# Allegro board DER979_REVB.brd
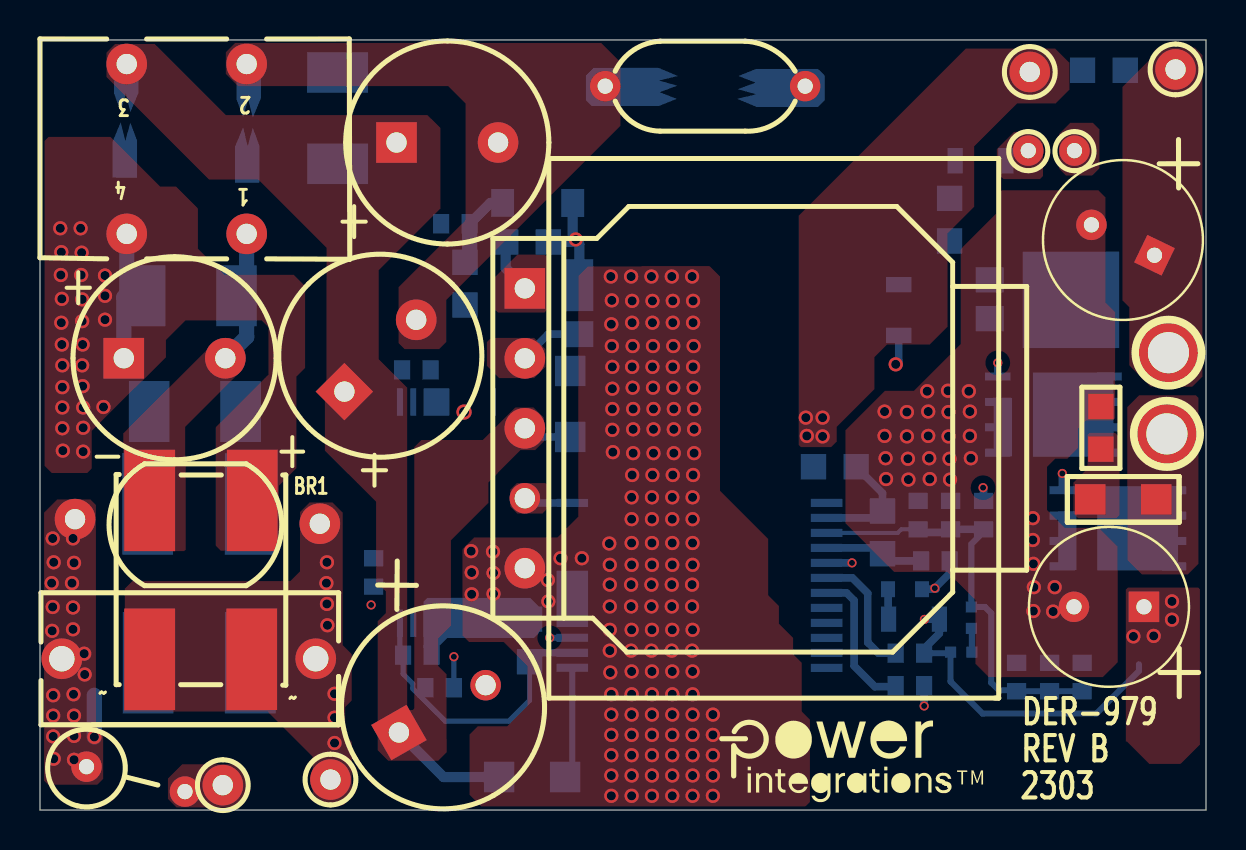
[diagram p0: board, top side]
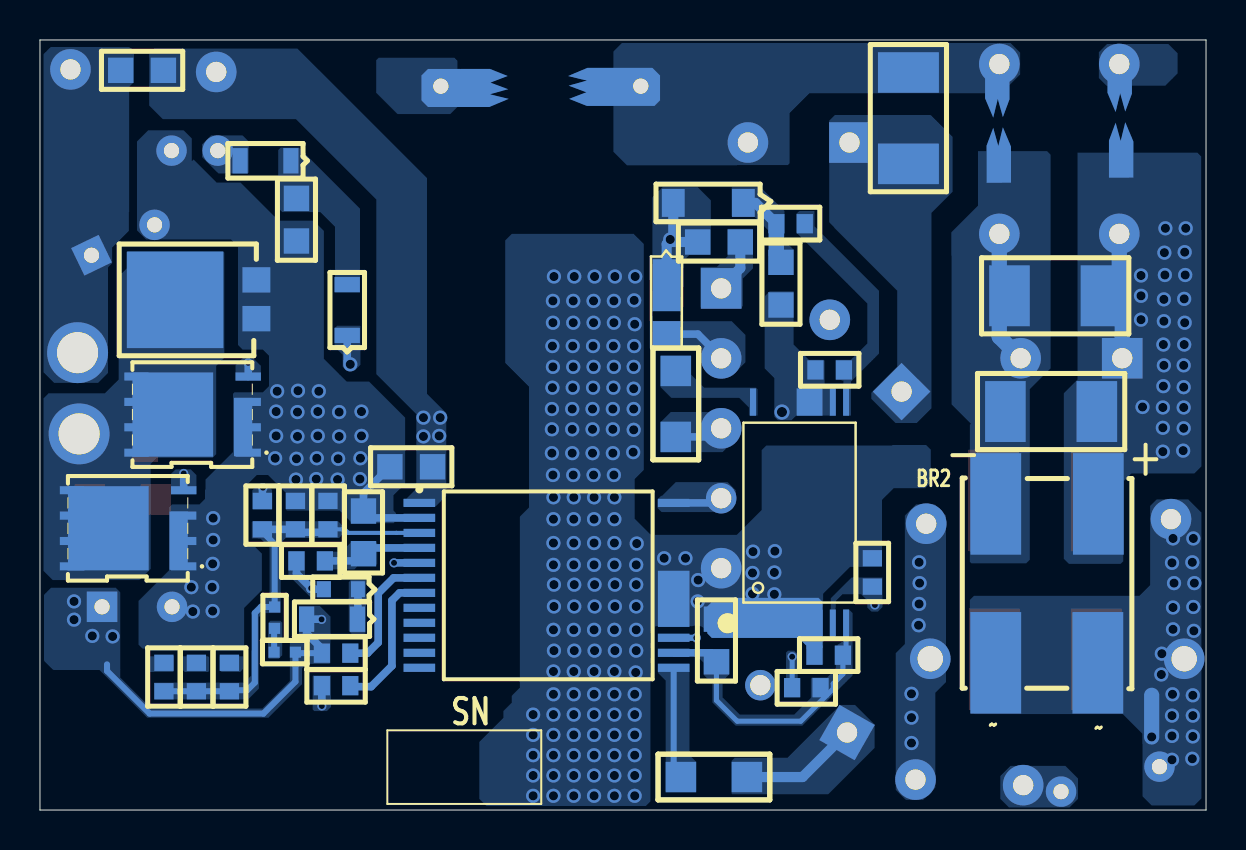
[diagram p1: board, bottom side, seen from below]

Outline 58.32 x 38.53 mm; copper layers: TOP, INNER1, INNER2, BOTTOM. Coordinates in mm from the lower left corner of the outline.
Outline path: 0,38.53 0,0 58.32,0 58.32,38.53 0,38.53

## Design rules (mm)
constraint set DEFAULT: min track width 0.203

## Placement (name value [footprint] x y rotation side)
BR1  Z4DGP406L-HF  [PI_SM_D_Z4D]  10.59 15.54 0 top
BR2  Z4DGP406L-HF  [PI_SM_D_Z4D]  5.41 15.37 180 bottom
C1  220 nF  [PINPXCAPRAD475X255500040]  13.79 7.57 180 top
C2  27 uF  [PIPOLCAPCYLD400LS200040]  4.19 22.61 0 top
C3  27 uF  [PIPOLCAPCYLD400LS200040]  15.22 20.94 45 top
C4  27 uF  [PIPOLCAPCYLD400LS200040]  17.83 33.4 0 top
C5  27 uF  [PIPOLCAPCYLD400LS200040#2]  17.95 3.88 29.7 top
C6  10 uF  [PISMC0805]  25.43 28.42 180 bottom
C7  0.1 uF  [PISMC0603]  18.11 22.02 0 bottom
C8  100 nF  [PISMC0603]  18.16 7.75 0 bottom
C9  100 nF  [PISMC1206]  26.52 18.67 90 bottom
C10  1 uF  [PISMC0805]  21.26 25.27 90 bottom
C11  0.47 uF  [PISMC0805]  24.49 7.42 90 bottom
C12  2.2 uF  [PISMC0805]  42.14 12.83 90 bottom
C13  2.2 nF  [PISMC0805]  53.06 20.19 270 top
C14  10 uF  [PISMC0805]  45.49 30.61 270 bottom
C15  680 uF  [PIPOLCAPCYLD8MMD030]  55.74 27.76 154.2 top
C16  680 uF  [PIPOLCAPCYLD8MMD030]  55.21 10.17 180 top
C17  10 nF  [PISMR0402]  46.58 9.09 90 bottom
C18  330 pF  [PISMC0603]  43.92 14.05 90 bottom
C19  1 uF  [PISMC0805]  52.15 37.01 0 bottom
C20  2200 pF  [PINPCAPRAD9MMXLS10MM030]  28.27 36.22 0 top
C21  470 nF  [PISMC1812]  5.26 25.73 0 bottom
C23  470 nF  [PISMC1812]  14.88 32.33 90 bottom
C24  470 nF  [PISMC1812]  5.46 19.94 0 bottom
D1  HS1KFL  [PI_SM_SOD-123_12]  23.14 30.38 0 bottom
D2  SS10200HE_R1_00001  [PI_SM_SOD-123HE]  26.97 26.26 270 bottom
D4  BAV21WS-7-F  [PISMSOD323]  45.77 32.49 0 bottom
D5  SDM2U20SD3-7  [PISMSOD323]  42.95 23.75 90 bottom
D6  BAV19WS  [PISMSOD323]  42.44 9.55 0 bottom
D7  FSV15100V  [PI_SM_D_TO-277A]  47.5 26.54 90 bottom
F1  6.3 A  [PI_V_AX_3-6X10_145LS200D030]  7.25 0.92 165.8 top
FL1  Hole_100mils  [PI_HOLE_100MIL]  56.36 18.82 0 top
FL2  Hole_100mils  [PI_HOLE_100MIL]  56.44 22.89 0 top
FL3  Hole_30mils  [PI_HOLE_30MIL]  49.43 32.99 0 top
FL4  Hole_30mils  [PI_HOLE_30MIL]  51.74 32.99 0 top
L1  6.2 mH  [PI_CMC_18MH_SUMIDA]  10.34 28.83 180 top
NOREF  -  []  33.99 4.95 0 top
NOREF#2  -  []  91.31 -222.55 0 top
NOREF#3  -  []  58.32 0 90 top
NOREF#4  -  []  -327.66 -235.53 0 top
NOREF#5  -  []  0 38.58 0 top
Q1  AON6290  [PISMPQFN5X6B]  51.13 12.19 90 bottom
Q2  AON6290  [PISMPQFN5X6B]  47.9 17.88 90 bottom
R1  1.3 k  [PISMR0603]  20.7 6.12 180 bottom
R2  2 k  [PISMR0603]  20.07 29.34 0 bottom
R3  15 k  [PISMR0603]  16.69 12.6 270 bottom
R4  3.3 M  [PISMR1206]  22.96 1.65 0 bottom
R5  47  [PISMR0603]  44.22 6.22 180 bottom
R6  0.0  [PISMR1206]  52.53 15.54 0 top
R7  33  [PISMR0603]  44.22 7.85 180 bottom
R8  0  [PISMR0805]  38.68 17.18 0 bottom
R12  0.0  [PISMR0603]  45.49 12.47 180 bottom
R13  51  [PISMR0402]  45.54 7.9 0 bottom
R14  100 k  [PISMR0603]  47.19 15.47 270 bottom
R15  33 K  [PISMR0603]  45.54 14.05 90 bottom
R16  31.6  [PISMR0603]  48.84 5.94 90 bottom
R17  8.25 k  [PISMR0603]  50.5 5.94 90 bottom
R18  12.4 k  [PISMR0603]  52.12 5.94 90 bottom
RV1  175 Vac  [PI_DISC_335X240LS200D040]  10.31 14.27 180 top
T1  ATQ27/14.4  [PI_BOBBIN_ATQ27_V_5P]  36.45 19.1 0 top
TP1  BLK  [PITPKEYSTONE100X100]  14.53 1.52 0 top
TP2  WHT  [PITPKEYSTONE100X100]  9.14 1.24 0 top
TP3  BLK  [PITPKEYSTONE100X100]  49.5 36.93 0 top
TP4  RED  [PITPKEYSTONE100X100]  56.79 37.06 0 top
U1  CPZ1172M  [PI_SM_MINSOP16A_1]  22.66 9.35 180 bottom
U2  INN4077C-H182  [PI_IC_INSOP_24D_IPC]  39.34 15.37 180 bottom
VR3  DZ2S300M0L  [PI_SM_D_SSMINI2P]  42.42 11.05 0 bottom

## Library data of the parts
BR1 BR2 = DISCRETE BRIDGE_+~~-
C1 C6 C20 C21 C23 C24 = CAP NP
C2-C5 = CAP POL: alternate symbols: (pipolcapclyd400x675ls200040h)
C7 = CAP NP: alternate symbols: (cc0603); room: 2
C8 C10 = CAP NP: room: 2
C9 = CAP NP: room: 1
C11-C14 C17 = CAP NP: room: 3
C15 C16 = CAP POL: alternate symbols: (pipolcapcyld8x16mmd030H); room: 3
C18 = CAP NP: alternate symbols: (pismc0603_1); room: 3
C19 = CAP NP: room: 4
D1 = DIODE: room: 2
D2 = DIODE SCHOTTKY: room: 1
D4 D6 = DIODE
D5 = DIODE SCHOTTKY
D7 = DIODE SCHOTTKY_TO-277A
F1 = FUSE: alternate symbols: (pi_axial_3_6x10_145ls500d030)
FL1 = FlyingLead
FL2-FL4 = FlyingLead: room: 3
L1 = TORRID 4P_12_43a: alternate symbols: (pi_CMC_18mH_SumidaW,pi_CMC_18mH_Sumida_H,pi_CMC_18mH_SumidaSF)
Q1 Q2 = FET_N_SGD_123_4_5678: room: 3
R1 R3 R4 = R: room: 2
R2 = R: alternate symbols: (pismr0603_1); room: 2
R5 = R: alternate symbols: (pismr0603_1); room: 4
R6 R7 R12-R18 = R: room: 3
R8 = R
RV1 = VARISTOR
T1 = BATQ27_5P/GENERIC
TP1 TP3 = TESTPOINT: alternate symbols: (TP_TH_CR2_D1_1)
TP2 TP4 = TESTPOINT
U1 = ClampZeroMinSOP16: room: 2
U2 = MinnoPriSecCZ: alternate symbols: (pi_ic_insop_24d,PI_IC_INSOP24B); room: 3
VR3 = DIODE_ZENER

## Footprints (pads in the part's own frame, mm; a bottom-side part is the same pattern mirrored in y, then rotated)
PI_BOBBIN_ATQ27_V_5P
  rect 2.032x2.032 hole 1.016: 1(-12.2,7)
  round 2.032 hole 1.016: 2(-12.2,3.5) 3(-12.2,0) 5(-12.2,-7)
  round 1.524 hole 1.016: 4(-12.2,-3.5)
PI_CMC_18MH_SUMIDA
  round 2.032 hole 1.016: 1(0,0) 2(0,-8.499) 3(5.999,-8.499) 4(5.999,0)
PI_DISC_335X240LS200D040
  round 2.032 hole 1.016: 1(-3.683,-0.051) 2(8.56,-0.279)
PI_HOLE_30MIL
  round 1.524 hole 0.762: 1(0,0)
PI_HOLE_100MIL
  round 3.048 hole 2.057: 1(0,0)
PI_IC_INSOP_24D_IPC
  rect 1.58x0.409 smd: 1(0,0) 2(0,-0.749) 3(0,-1.501) 4(0,-2.25) 5(0,-3) 6(0,-3.749) 7(0,-4.501) 8(0,-5.25) 9(0,-5.999) 10(0,-6.749) 11(0,-7.501) 12(0,-8.25) 13(12.72,-8.25) 14(12.72,-7.501) 15(12.72,-6.749) 24(12.72,0)
  rect 1.58x2.809 smd: 16(12.72,-4.801)
PI_SM_D_SSMINI2P
  rect 0.699x0.8 smd: 1(0,0) 2(1.699,0)
PI_SM_D_TO-277A
  rect 1.27x1.397 smd: 1(-0.015,0) 2(-1.956,0)
  rect 4.826x4.826 smd: 3(-1.016,4.064)
PI_SM_D_Z4D
  rect 2.54x5.08 smd: 1(0.025,-0.051) 2(0,-8.001) 3(-5.105,-8.001) 4(-5.105,-0.051)
PI_SM_MINSOP16A_1
  rect 0.3x1.369 smd: 1(0,0) 2(0.665,0) 3(1.331,0) 4(1.994,0) 5(2.659,0) 6(3.325,0) 7(3.99,0) 8(4.656,0) 9(4.656,11.067) 10(3.99,11.067) 16(0,11.067)
  rect 1.293x1.369 smd: 11(2.83,11.067)
PI_SM_SOD-123_12
  rect 1.143x1.397 smd: 1(0,0) 2(3.505,0)
PI_SM_SOD-123HE
  rect 2.601x1.4 smd: 1(0,0)
  rect 1.3x1.4 smd: 2(2.451,0)
PI_V_AX_3-6X10_145LS200D030
  round 1.524 hole 0.762: 1(0,0) 2(5.08,0)
PINPCAPRAD9MMXLS10MM030
  round 1.524 hole 0.762: 1(0,0) 2(10,0)
PINPXCAPRAD475X255500040
  round 2.032 hole 1.27: 1(0,0) 2(12.7,0)
PIPOLCAPCYLD8MMD030
  rect 1.524x1.524 hole 0.762: 1(0,0)
  round 1.524 hole 0.762: 2(3.5,0)
PIPOLCAPCYLD400LS200040
  rect 2.032x2.032 hole 1.016: 1(0,0)
  round 2.032 hole 1.016: 2(5.08,0)
PIPOLCAPCYLD400LS200040#2
  rect 2.032x2.032 hole 1.016: 1(0,0)
  round 1.524 hole 1.016: 2(4.94,-0.094)
PISMC0603
  rect 0.813x0.965 smd: 1(0,0) 2(1.422,0)
PISMC0805
  rect 1.27x1.27 smd: 1(0,0) 2(2.134,0)
PISMC1206
  rect 1.524x1.524 smd: 1(0,0) 2(3.302,0)
PISMC1812
  rect 2.032x3.048 smd: 1(0,0) 2(4.572,0)
PISMPQFN5X6B
  rect 0.406x1.27 smd: 1(0,0) 2(1.27,0) 3(2.54,0) 4(3.81,0)
  rect 0.406x1.219 smd: 5(3.81,5.588) 6(2.54,5.588) 7(1.27,5.588) 8(0,5.588)
PISMR0402
  rect 0.559x0.559 smd: 1(0,0) 2(1.067,0)
PISMR0603
  rect 0.813x0.965 smd: 1(0,0) 2(1.422,0)
PISMR0805
  rect 1.27x1.27 smd: 1(0,0) 2(2.134,0)
PISMR1206
  rect 1.524x1.524 smd: 1(0,0) 2(3.302,0)
PISMSOD323
  rect 0.762x1.27 smd: 1(0,0) 2(2.54,0)
PITPKEYSTONE100X100
  round 2.032 hole 1.016: 1(0,0)

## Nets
GND: C12.2 C13.1 C14.2 C15.2 C16.2 C18.2 D7.1 D7.2 FL4.1 Q1.1 Q1.2 Q1.3(S3) Q2.1 Q2.2 Q2.3(S3) R8.2 R15.2 U2.2
RTN: C19.1 R8.1 TP3.1 U2.1
VOUT: C15.1 C16.1 C19.2 C20.2 D6.2 FL2.1 R7.1 R13.1 R14.1 TP4.1
N10971121: C8.1 C11.1 R1.2 U1.8 U2.14
N10972629: C17.2 C18.1 R14.2 R15.1 R16.1 R17.1 R18.1 U2.3
N10986441: R4.2 U2.13
N10993526: C7.2 C10.1 T1.4 U1.10 U1.11(S2-11) U2.24
N11033773: C3.2 C4.2 C5.2 C6.2 C8.2 C11.2 C20.1 C23.2 L1.2 R3.1 T1.1 T1.5 U1.3 U1.6 U2.16
N11038315: C3.1 C4.1 C5.1 C9.1 C23.1 L1.3 R4.1 T1.3
N11038383: C9.2 U1.16
N11093530: D7.3(CATHODE) FL1.1 Q1.5 Q1.6 Q1.7 Q1.8 Q2.5 Q2.6 Q2.7 Q2.8 R5.1 R6.2
N11118683: R3.2 U1.7 U2.15
N11129317: R5.2 U2.7
N11134278: Q1.4 Q2.4 U2.5
N11138918: C17.1 R13.2
N11256131: C7.1 R2.1 U1.9
N11484512: R7.2 U2.6
N11515908: C10.2 D1.1 R2.2
N12555875: C12.1 R12.2 U2.4
N13144639: C13.2 R6.1
N13180601: C14.1 D4.1 D5.2
N13197624: D4.2 FL3.1
N13230820: D2.2 T1.2
N13361044: C6.1 D1.2 D2.1 R1.1
N13388475: BR1.1 BR2.1 C2.1 C21.1 C24.1 L1.4
N13388575: BR1.2 BR1.3(AC2) C1.1 RV1.1 TP1.1
N13388715: BR1.4 BR2.4 C2.2 C21.2 C24.2 L1.1
N13388781: BR2.2 BR2.3(AC2) C1.2 F1.2 RV1.2
N13388817: F1.1 TP2.1
N13395881: D5.1 R12.1 VR3.2
N13397632: D6.1 VR3.1

Pads without a net: R16 2; R17 2; R18 2; U1 1 2 4 5; U2 8 9 10 11 12

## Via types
v1: diameter 0.457, hole 0.305, TOP to BOTTOM, 10 vias
v2: diameter 0.711, hole 0.457, TOP to BOTTOM, 230 vias
v3: diameter 0.762, hole 0.508, TOP to BOTTOM, 1 via

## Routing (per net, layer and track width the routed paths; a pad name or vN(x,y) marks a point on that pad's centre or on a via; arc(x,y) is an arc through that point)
GND: length 8.2
  BOTTOM w0.203: Q1.1 Q1.2 Q1.3
  BOTTOM w0.381: U2.2 41.8,14.62 C12.2 42.14,15.85 R8.2
  vias: v2(42.24,19.94) v2(42.24,18.72) v2(42.29,17.6) v2(42.32,16.56) v2(43.36,19.91) v2(43.36,18.69) v2(43.41,17.58) v2(43.43,16.54) v2(44.37,20.95) v2(44.42,19.94) v2(44.42,18.72) v2(44.48,17.6) v2(44.5,16.56) v2(45.42,20.98) v2(45.44,19.91) v2(45.44,18.69) v2(45.49,17.58) v2(45.52,16.54) v2(46.46,20.95) v2(46.51,19.94) v2(46.51,18.72) v2(46.56,17.6) v2(49.66,14.61) v2(49.66,13.51) v2(49.68,12.32) v2(49.71,11.15) v2(49.68,9.96) v2(50.75,11.15) v2(50.67,9.93)
RTN:
  vias: v2(38.3,19.63) v2(38.35,18.72) v2(39.14,19.63) v2(39.14,18.69)
VOUT: length 45.4
  INNER1 w0.381: v1(47.17,16.13) 46.69,15.65 46.69,11.66 44.56,9.54 v1(44.23,9.54)
  INNER2 w0.203: TP4.1 54.89,37.06 52.68,34.85 39.73,34.85 38.38,36.2
  BOTTOM w0.305: R7.1 45.49,7.85 R13.1 45.54,6.43 47.14,4.83 52.83,4.83 54.97,6.96 54.97,7.29
  BOTTOM w0.381: R7.1 44.22,8.08 44.98,8.84 D6.2 44.25,9.55 v1(44.23,9.54) ; R14.1 47.19,16.1 v1(47.17,16.13)
  vias: v2(54.69,8.69) v2(55.7,8.71) v2(56.62,10.44) v2(56.62,9.53)
N10971121: length 14.8
  BOTTOM w0.254: C11.1 24.49,5.49 23.44,4.45 20.27,4.45 18.64,6.07 18.64,6.32 18.16,6.81 C8.1 18,7.91 U1.8
  BOTTOM w0.381: C11.1 24.49,7.59 24.76,7.87 U2.14
N10972629: length 21.5
  BOTTOM w0.203: C18.1 43.08,14.05 42.9,13.87 40.49,13.87 40.49,13.87 U2.3
  BOTTOM w0.305: R14.2 47.19,13.92 46.58,13.31 C17.2 47.27,10.16 47.57,9.86 47.57,6.38 47.96,5.99 48.79,5.99 R16.1 R17.1 R18.1
  BOTTOM w0.381: R14.2 45.69,14.05 45.67,14.02 45.57,14.02 R15.1 45.54,14.02 45.42,13.89 44.07,13.89 C18.1
N10986441: length 5.6
  BOTTOM w0.305: U2.13 26.62,2.01 R4.2
N10993526: length 2.5
  BOTTOM w0.381: 24.25,15.65 24.54,15.37 U2.24
  vias: v3(21.21,19.91)
N11033773: length 13.2
  INNER1 w0.762: 18.82,24.53 18.82,25.7 22.91,29.79 C4.2
  BOTTOM w0.508: C6.2 23.29,27.11 24.25,26.15
  vias: v2(21.56,12.95) v2(21.59,11.89) v2(21.59,10.79) v2(22.66,12.93) v2(22.68,11.86) v2(22.68,10.82) v2(25.4,11.51) v2(25.43,10.44) v2(26.04,12.6) v2(27.1,12.6) v2(28.55,26.7) v2(28.47,13.34) v2(28.5,12.27) v2(28.5,11.28) v2(28.5,10.19) v2(28.5,9.02) v2(28.5,7.98) v2(28.52,6.88) v2(28.6,25.5) v2(28.57,24.31) v2(28.6,23.22) v2(28.63,22.17) v2(28.63,21.08) v2(28.63,20.07) v2(28.63,19.02) v2(28.57,5.79) v2(28.57,4.78) v2(28.57,3.76) v2(28.57,2.74) v2(28.57,1.73) v2(28.57,0.71) v2(28.65,17.91) v2(29.57,26.7) v2(29.62,25.48) v2(29.62,24.38) v2(29.64,23.22) v2(29.62,22.17) v2(29.64,21.13) v2(29.62,16.76) v2(29.59,15.65) v2(29.59,14.55) v2(29.59,13.36) v2(29.59,12.27) v2(29.57,11.28) v2(29.57,10.19) v2(29.59,9.02) v2(29.57,7.98) v2(29.59,6.93) v2(29.59,5.79) v2(29.59,4.78) v2(29.59,3.76) v2(29.59,2.74) v2(29.59,1.73) v2(29.59,0.71) v2(29.67,20.07) v2(29.67,19.05) v2(29.67,17.86) v2(30.58,26.7) v2(30.63,25.48) v2(30.63,24.38) v2(30.63,22.17) v2(30.63,16.76) v2(30.61,15.65) v2(30.61,14.55) v2(30.61,13.36) v2(30.61,12.27) v2(30.58,11.28) v2(30.58,10.19) v2(30.61,9.02) v2(30.58,7.98) v2(30.61,6.93) v2(30.61,5.79) v2(30.61,4.78) v2(30.61,3.76) v2(30.61,2.74) v2(30.61,1.73) v2(30.61,0.71) v2(30.66,23.22) v2(30.66,21.13) v2(30.68,20.07) v2(30.68,19.05) v2(30.68,17.86) v2(31.6,26.7) v2(31.65,25.48) v2(31.65,24.38) v2(31.65,22.17) v2(31.65,16.76) v2(31.62,15.65) v2(31.62,14.55) v2(31.62,13.36) v2(31.62,12.27) v2(31.6,11.28) v2(31.6,10.19) v2(31.62,9.02) v2(31.6,7.98) v2(31.62,6.93) v2(31.62,5.79) v2(31.62,4.78) v2(31.62,3.76) v2(31.62,2.74) v2(31.62,1.73) v2(31.62,0.71) v2(31.67,23.22) v2(31.67,21.13) v2(31.7,20.07) v2(31.7,19.05) v2(31.7,17.86) v2(32.61,26.7) v2(32.64,15.65) v2(32.64,14.55) v2(32.64,13.36) v2(32.64,12.27) v2(32.61,11.28) v2(32.61,10.19) v2(32.64,9.02) v2(32.61,7.98) v2(32.64,6.93) v2(32.64,5.79) v2(32.64,4.78) v2(32.64,3.76) v2(32.64,2.74) v2(32.64,1.73) v2(32.64,0.71) v2(32.66,25.48) v2(32.66,24.38) v2(32.69,23.22) v2(32.66,22.17) v2(32.69,21.13) v2(32.72,20.07) v2(32.72,19.05) v2(32.72,17.86) v2(32.66,16.76) v2(33.66,4.78) v2(33.66,3.76) v2(33.66,2.74) v2(33.66,1.73) v2(33.66,0.71)
N11038315: length 8.4
  BOTTOM w0.381: 24.25,19.15 24.74,18.67 C9.1
  BOTTOM w0.508: C5.1 20.18,1.65 R4.1
N11093530: length 17.5
  INNER1 w0.381: v1(44.22,5.21) 44.22,6.81 48.13,10.72 48.13,14.66 49.45,15.98 53.01,15.98
  BOTTOM w0.381: R5.1 v1(44.22,5.21)
N11118683: length 10.7
  INNER2 w0.305: v1(16.56,10.26) 17.32,9.5 20.65,9.5 21.53,8.62 v1(25.49,8.62)
  BOTTOM w0.305: U2.15 v1(25.49,8.62)
N11129317: length 7.3
  BOTTOM w0.381: U2.7 40.34,10.87 40.72,10.49 40.72,7.21 41.76,6.17 42.75,6.17 R5.2
N11134278: length 27.4
  INNER1 w0.381: 47.9,16.84 47.9,15.6 47.45,15.14 47.45,11.33 44.86,8.74 43.03,8.74 40.61,11.15 v1(40.61,12.37) ; 47.9,16.84 v1(51.13,16.84) ; 47.9,16.84 v1(47.9,22.38)
  BOTTOM w0.381: Q1.4 v1(51.13,16.84) ; Q2.4 v1(47.9,22.38) ; U2.5 v1(40.61,12.37)
N11138918: length 1.2
  BOTTOM w0.305: C17.1 46.61,9.07 R13.2
N11484512: length 6.5
  BOTTOM w0.381: R7.2 41.94,7.85 41.4,8.38 41.4,10.85 40.63,11.62 U2.6
N11515908: length 4.1
  BOTTOM w0.508: R2.2 22.53,30.38 D1.1
  BOTTOM w0.762: R2.2 21.49,27.81 21.26,27.58 C10.2
N12555875: length 5
  BOTTOM w0.381: U2.4 41.85,13.12 C12.1 42.5,12.47 R12.2
N13230820: length 3.2
  BOTTOM w0.381: 24.25,22.65 25.42,23.81 D2.2
N13361044: length 33.4
  INNER1 w0.381: v1(20.7,7.67) 19.62,8.75 19.62,21.37 21.87,23.62 21.87,26.72 23.7,28.55 v2(26.8,28.55)
  BOTTOM w0.254: R1.1 v1(20.7,7.67)
  BOTTOM w0.508: D2.1 26.97,28.32 26.87,28.42 ; D1.2 26.64,28.65 26.87,28.42 ; 26.87,28.42 C6.1
N13388475: length 6.3
  BOTTOM w0.762: C2.1 4.19,25.66 4.34,25.81 L1.4
  vias: v2(1.02,29.11) v2(1.04,26.77) v2(1.07,27.91) v2(1.09,25.58) v2(1.07,24.38) v2(1.09,23.29) v2(1.12,22.25) v2(1.12,21.16) v2(1.12,20.14) v2(1.12,19.1) v2(1.14,17.98) v2(2.03,29.11) v2(2.08,27.89) v2(2.06,26.77) v2(2.11,25.55) v2(2.11,24.46) v2(2.13,23.29) v2(2.11,22.25) v2(2.13,21.21) v2(2.16,20.14) v2(2.16,19.13) v2(2.16,17.93) v2(3.17,20.17) v2(3.25,26.75) v2(3.25,25.73) v2(3.25,24.54)
N13388575:
  vias: v2(14.33,11.35) v2(14.35,12.4) v2(14.35,10.31) v2(14.38,9.25) v2(14.73,5.82) v2(14.73,4.62) v2(14.73,3.35)
N13388715: length 6.7
  BOTTOM w0.762: L1.1 10.34,23.67 C2.2
N13388781: length 2.1
  BOTTOM w0.762: 2.72,5.74 v2(2.72,3.66)
  vias: v2(0.64,13.59) v2(0.58,11.35) v2(0.64,10.16) v2(0.61,8.97) v2(0.69,12.4) v2(0.66,5.74) v2(0.66,4.72) v2(0.66,3.68) v2(0.69,2.57) v2(1.6,11.35) v2(1.65,13.59) v2(1.7,12.37) v2(1.65,10.13) v2(1.65,9.04) v2(1.68,5.79) v2(1.7,4.72) v2(1.7,3.71) v2(1.7,2.51) v2(2.21,7.82) v2(2.24,6.78)
N13395881: length 17.9
  INNER1 w0.381: v2(42.8,22.3) 40.49,19.99 40.49,15.37 v1(44.75,11.1)
  BOTTOM w0.381: v2(42.8,22.3) 42.95,22.45 D5.1 ; R12.1 45.49,11.84 v1(44.75,11.1) 44.81,11.05 VR3.2
N13397632: length 1.5
  BOTTOM w0.381: VR3.1 42.42,9.58 D6.1

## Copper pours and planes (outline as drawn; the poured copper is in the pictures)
GND on BOTTOM (solid shape): 48.62,17.7 47.7,17.7 47.7,20.62 48.62,20.62
GND on BOTTOM (solid shape): 51.84,12.01 50.93,12.01 50.93,14.94 51.84,14.94
GND on TOP: 52.98,32.11 52.63,31.75 51.31,31.75 50.98,32.08 50.98,33.83 51.54,34.39 52.65,34.39 52.98,34.06
GND on TOP: 53.29,25.4 53.77,24.92 53.77,19.61 53.64,19.48 52.3,19.48 51.92,19.1 51.92,18.11 51.38,17.58 50.77,17.58 50.37,17.17 50.37,15.01 51.26,14.12 52.96,14.12 53.9,13.18 53.9,7.39 53.16,6.65 47.45,6.65 46.79,7.32 46.79,10.52 45.39,11.91 42.72,11.91 40.28,14.35 40.28,19 42.27,20.98 43.71,20.98 46.05,23.32 46.05,28.07 48.03,30.05 48.03,30.94 48.11,31.01 52.93,31.01 53.29,30.66
GND on BOTTOM: 53.47,29.01 53.01,28.55 48.77,28.55 48.41,28.19 48.41,23.27 48.18,23.04 47.17,23.04 46.86,22.73 46.86,21.21 47.17,20.9 48.59,20.9 48.67,20.83 48.67,17.91 50.04,16.54 50.04,16.05 50.06,16.03 50.06,15.57 50.34,15.29 51.71,15.29 51.85,15.15 51.85,12 53.39,10.46 53.39,8.28 53.19,8.08 48.18,8.08 48.11,8.15 48.11,10.11 47.22,11 47.22,12.83 47.6,13.21 47.96,13.21 48.11,13.36 48.11,16.13 47.47,16.76 46.91,16.76 46.02,15.88 46.02,15.04 45.97,14.99 43.33,14.99 42.67,14.33 40.67,14.33 40.56,14.43 38.56,14.43 38.56,14.83 40.49,14.83 40.64,14.99 40.64,15.75 40.06,16.33 40.06,19.63 41.86,21.44 42.98,21.44 44.12,22.58 44.12,28.98 44.63,29.49 46.38,29.49 48.29,31.39 49.48,31.39 50.67,32.59 50.67,32.51 50.72,32.46 50.72,33.6 51.13,34.01 52.91,34.01 53.47,33.45
GND on INNER1: 41.05,19.58 42.39,20.93 43.13,20.93 44.2,22 44.2,26.47 48.82,31.09 52.63,31.09 53.42,30.3 53.42,25.48 50.6,25.48 48.16,23.04 47.65,23.04 47.29,22.68 47.29,17.3 46.13,16.13 46.13,13.31 45.49,12.67 44.37,12.67 41.05,16
GND on INNER1: 53.72,8.64 52.86,7.77 49.35,7.77 48.82,8.31 48.82,14.22 49.83,15.24 50.93,15.24 51.13,15.04 51.13,12.17 52.04,11.25 53.54,11.25 53.72,11.07
GND on INNER2: 53.57,25.65 52.86,24.94 50.75,24.94 50.44,24.64 50.44,22.35 49.95,21.86 49.95,19.16 49.96,19.15 49.96,16.89 53.44,13.41 53.44,3.02 52.88,2.46 47.55,2.46 47.04,2.97 47.04,11.28 46.34,11.98 42.2,11.98 40.92,13.26 40.92,20.09 40.93,20.1 40.93,28.89 42.44,30.4 53.34,30.4 53.57,30.18
Net_42 on BOTTOM: 51.61,7.8 51.61,6.96 51.66,6.91 52.91,6.91 52.98,6.99 52.98,7.62 52.78,7.82 51.64,7.82
Net_43 on BOTTOM: 49.86,7.65 49.86,6.96 49.91,6.91 51.08,6.91 51.18,7.01 51.18,7.67 51.03,7.82 50.04,7.82
Net_44 on BOTTOM: 48.13,7.72 48.13,7.09 48.31,6.91 49.25,6.91 49.33,6.99 49.33,7.7 49.2,7.82 48.23,7.82
RTN on TOP: 45.39,28.85 45.39,24.18 44.5,23.29 42.37,23.29 41.73,22.66 41.73,21.06 39.85,19.18 39.85,18.44 39.6,18.19 39.6,18.16 38.05,18.16 37.95,18.26 37.95,29.74 46.3,38.1 50.77,38.1 51.49,37.39 51.49,36.04 50.8,35.36 48.87,35.36 46.72,33.21 46.72,30.19
RTN on BOTTOM: 38,15.72 38,19.86 38.96,20.83 38.96,31.62 45.44,38.1 52.58,38.1 52.86,37.82 52.86,35.26 52.17,34.57 45.52,34.57 41.5,30.55 41.5,21.81 39.5,19.81 39.5,16.08 40.01,15.57 40.11,15.57 40.13,15.54 40.13,15.16 38.56,15.16
RTN on INNER1: 43.36,26.95 43.36,24.08 39.6,20.32 39.6,18.21 39.37,17.98 38.15,17.98 37.88,18.25 37.88,31.94 44.04,38.1 50.83,38.1 51.54,37.39 51.54,36.09 50.83,35.38 48.84,35.38 47.47,34.01 47.47,31.06
VOUT on BOTTOM (solid shape): 37.3,37.07 37.31,37.08 38.91,37.08 39.24,36.75 39.24,35.51 38.91,35.18 35.84,35.18 34.87,35.59 35.81,35.81 34.9,36.07 35.79,36.4 34.92,36.73 35.81,37.08 37.29,37.08
VOUT on TOP: 54.41,11.13 57.94,11.13 58.01,11.05 58.01,3.28 57.05,2.31 55.47,2.31 54.36,3.43 54.33,3.43 54.31,3.4 54.31,11.02
VOUT on TOP: 54.14,36.18 56.11,38.15 57.76,38.15 58.14,37.77 58.14,21.69 57.63,21.18 55.55,21.18 54.48,22.25 54.48,25.16 54.14,25.5
VOUT on BOTTOM: 43.79,7.37 43.79,9.68 44.32,10.21 45.36,10.21 45.36,8.81 45.82,8.36 45.82,6.45 47.19,5.08 52.76,5.08 54.31,6.63 54.31,7.04 54.66,7.39 55.17,7.39 55.37,7.19 55.37,7.04 52.96,4.62 46.89,4.62 45.21,6.3 45.21,7.09 44.98,7.32 43.84,7.32
VOUT on BOTTOM: 54.31,10.9 54.31,7.01 57.66,7.01 58.12,7.47 58.12,10.77 57.73,11.15 54.56,11.15
VOUT on BOTTOM: 53.62,36.42 53.62,37.95 53.85,38.18 57.78,38.18 58.14,37.82 58.14,21.9 57.98,21.75 57.61,21.37 55.41,21.37 54.91,21.87 54.91,27.15 54.71,27.36 54.71,28.14 53.87,28.98 53.87,29.92 53.86,29.93 53.86,36.18
VOUT on BOTTOM: 37.44,35.18 37.8,34.82 40.44,34.82 41.5,35.89 41.5,37.52 41.38,37.64 37.59,37.64 37.44,37.49
VOUT on BOTTOM: 47.65,15.01 47.7,15.06 47.7,16.1 47.45,16.36 46.96,16.36 46.71,16.1 46.71,15.01
VOUT on INNER1: 57.89,38.05 58.12,37.82 58.12,21.67 57.89,21.44 55.65,21.44 55.65,21.46 54.58,22.53 54.58,24.73 53.91,25.4 53.91,25.58 53.92,25.59 53.92,37.8 54.18,38.05
VOUT on INNER1: 54.36,11 54.36,8.15 52.88,6.68 52.88,4.34 54.18,3.05 57.99,3.05 58.09,3.15 58.09,10.82 57.76,11.15 54.51,11.15
VOUT on INNER2: 52.96,34.32 38.66,34.32 37.62,35.36 37.62,37.62 38,38 45.52,38 47.17,36.35 47.17,36.3 48.16,35.31 51.59,35.31 54.46,38.18 57.81,38.18 58.17,37.82 58.17,21.74 57.28,20.85 55.07,20.85 53.95,19.74 53.95,17.88 55.27,16.56 57.25,16.56 58.14,15.67 58.14,12.55 58.14,12.54 58.14,8.1 57.81,7.77 54.86,7.77 54.13,8.51 54.13,14.86 50.57,18.41 50.57,21.51 51.08,22.02 51.08,24.36 51.23,24.51 53.64,24.51 54.18,25.04 54.18,33.1
N10971121 on BOTTOM: 18.14,8.79 18.14,8.56 18.52,8.18 18.52,7.06 18.95,6.63 19.71,6.63 19.76,6.58 19.76,5.61 20.6,4.78 23.32,4.78 24.18,5.64 24.18,6.45 23.83,6.81 23.83,8.05 26.54,8.05 26.59,8 26.59,7.67 26.57,7.65 25.4,7.65 25.12,7.37 25.12,6.76 24.69,6.32 24.69,5.38 23.52,4.22 20.19,4.22 17.68,6.73 17.68,9.86 17.86,10.03 18.16,10.03 18.16,8.81
N10972629 on BOTTOM: 47.68,14.45 47.73,14.4 47.73,13.59 47.71,13.58 47.28,13.58 46.84,13.13 46.84,10.82 47.75,9.91 47.75,6.73 48.11,6.38 52.6,6.38 52.6,5.54 47.9,5.54 47.37,6.07 47.37,9.65 47.17,9.86 46.3,9.86 46.28,9.88 46.28,13.36 46.02,13.61 43.36,13.61 43.1,13.87 43.1,14.15 43.41,14.45
N10986441 on BOTTOM: 25.5,0.91 25.5,2.41 25.83,2.74 25.83,7.32 27.41,7.32 27.41,6.86 27.03,6.48 27.03,0.97 26.97,0.91
N10993526 on TOP: 23.85,16.36 25.27,16.36 25.4,16.23 25.4,15.11 25.12,14.83 23.88,14.83 23.52,15.19 23.52,16.03
N10993526 on BOTTOM: 23.93,14.91 27.23,14.91 27.43,15.11 27.43,15.54 27.25,15.72 27.2,15.72 26.52,16.41 23.93,16.41 23.52,16 23.52,15.32
N10993526 on BOTTOM: 18.52,21.11 18.95,21.11 19.08,21.23 19.08,22.48 19.13,22.53 19.86,22.53 20.62,23.29 20.62,25.96 21.82,25.96 22.07,25.7 22.07,22.1 21.59,21.62 21.59,19.68 21.41,19.51 20.73,19.51 20.5,19.74 18.52,19.74
N10993526 on INNER1: 23.09,14.88 24.56,14.88 25.02,15.34 25.02,16 24.61,16.41 22.99,16.41 21.89,17.5 21.89,20.22 21.77,20.35 21.08,20.35 20.83,20.09 20.83,17.14
N11033773 on BOTTOM (solid shape): 11.05,37.42 11.05,35.61 10.64,34.65 10.41,35.59 10.16,34.67 9.83,35.56 9.83,35.55 9.83,37.41 9.84,37.42 10.41,37.42
N11033773 on BOTTOM (solid shape): 24.94,10.19 24.94,8.84 24.71,8.61 20.37,8.61 19.96,8.2 19.96,8.08 19.23,8.08 19.18,8.13 19.18,10.41 19.38,10.62 24.51,10.62
N11033773 on BOTTOM (solid shape): 31.9,36.73 30.96,36.5 31.88,36.25 30.99,35.92 31.85,35.59 30.96,35.23 27.58,35.23 27.3,35.51 27.3,36.75 27.69,37.13 30.94,37.13
N11033773 on TOP: 27.41,27.2 30.07,27.2 30.09,27.22 33.49,27.22 34.01,26.7 34.01,15.98 36.42,13.56 36.42,10.74 36.96,10.21 36.96,9.32 37.67,8.61 37.67,7.8 38.1,7.37 38.1,4.93 38.51,4.52 38.51,0.41 38.28,0.18 22.07,0.18 21.49,0.76 21.49,3.78 21.89,4.19 23.37,4.19 24.38,5.21 24.38,7.21 23.19,8.41 21.46,8.41 21.13,8.74 21.13,13.06 21.72,13.64 25.88,13.64 26.92,14.68 26.92,26.72
N11033773 on TOP: 23.24,27.18 23.24,27.15 22.63,26.54 22.63,25.17 22.91,24.89 25.22,24.89 25.4,25.07 25.4,27.64 25.25,27.79 23.88,27.79 23.27,27.18
N11033773 on TOP: 28.07,38.38 29.03,37.41 29.03,34.24 20.32,25.53 20.32,23.42 19.96,23.06 18.24,23.06 17.93,23.37 17.93,26.16 21.29,29.51 21.29,35.36 20.42,36.22 9.91,36.22 9.3,36.83 9.3,37.92 9.75,38.38
N11033773 on BOTTOM: 29.21,38.38 29.64,37.95 29.64,32.94 28.96,32.26 23.47,32.26 23.46,32.27 20.92,32.27 20.83,32.36 20.83,34.87 19.84,35.86 10.24,35.86 9.3,36.8 9.3,37.9 9.78,38.38
N11033773 on BOTTOM: 28.12,17.02 28.57,16.56 28.57,14.58 27.76,13.77 23.47,13.77 22.23,15.01 22.23,18.01 22,18.24 15.72,18.24 15.7,18.26 14,18.26 13.77,18.03 13.77,16.38 14.05,16.1 15.62,16.1 16.21,15.52 16.21,12.17 17.81,12.17 19.15,10.82 19.15,7.29 19.96,7.29 19.96,8.18 19.86,8.28 19.48,8.28 19.48,9.63 19.66,9.8 20.9,9.8 21.16,9.55 21.16,8.61 21.51,8.61 21.51,9.47 21.79,9.75 23.06,9.75 23.52,9.3 23.52,8.92 23.6,8.84 24.89,8.84 25.25,9.19 27.46,9.19 27.79,8.86 27.79,0.43 28.02,0.2 35.99,0.2 36.35,0.56 36.35,3.4 35.14,4.61 35.14,4.95 34.72,5.37 34.72,5.71 34.32,6.12 34.32,14.68 33.86,15.14 33.86,21.18 35.05,22.38 35.05,28.5 34.72,28.83 28.63,28.83 28.12,28.32
N11033773 on BOTTOM: 23.93,29.08 23.93,27.71 24.46,27.18 25.27,27.18 25.27,25.17 25.25,25.15 23.24,25.15 23.16,25.22 23.16,26.59 22.66,27.1 22.66,29.06 22.68,29.08
N11033773 on INNER1: 27.15,27.2 27.89,27.94 32.87,27.94 33.63,27.18 33.63,15.29 36.47,12.45 36.47,9.78 37.62,8.64 37.62,0.89 36.86,0.13 22.48,0.13 21.95,0.66 21.95,3.38 17.48,7.85 17.48,21.44 16.52,22.39 16.52,24.42 21.29,29.18 21.29,35.31 20.4,36.2 9.91,36.2 9.3,36.8 9.3,37.92 9.75,38.38 24,38.38 25.17,37.21 25.17,31.37 21.1,27.3 21.1,24.06 18.97,21.93 18.97,8.43 20.65,6.76 21.56,6.76 21.84,7.04 21.84,7.75 20.95,8.64 20.95,13.23 21.48,13.75 25.26,13.75 26.09,14.58 26.09,23.77 25.25,24.61 23.65,24.61 23.24,25.02 23.24,27.13 23.32,27.2
N11033773 on INNER2: 25.17,38.38 26.44,37.11 26.44,31.65 22.81,28.02 22.73,28.02 20.32,25.6 20.32,23.42 19.96,23.06 18.24,23.06 17.68,23.62 17.68,25.91 21.26,29.49 21.26,35.38 20.42,36.22 9.91,36.22 9.3,36.83 9.3,37.9 9.78,38.38
N11033773 on INNER2: 27.36,27.3 27.84,27.79 27.84,29.24 28.35,29.74 35.13,29.74 36.3,28.57 36.3,23.65 34.04,21.39 34.04,17.86 34.07,17.82 34.07,15.89 36.63,13.34 36.63,9.53 37.55,8.6 37.55,7.68 38.18,7.06 38.18,4.67 39.65,3.2 39.65,0.64 39.17,0.15 23.67,0.15 23.32,0.51 23.32,2.72 24.43,3.84 24.43,7.32 24.92,7.8 26.21,7.8 26.52,8.1 26.52,9.27 26.09,9.7 22.1,9.7 21.44,10.36 17.09,10.36 16.74,10.72 16.74,17.91 17.28,18.45 22.34,18.45 22.76,18.03 22.76,14.78 23.5,14.05 25.22,14.05 25.22,14.1 25.98,14.86 25.98,23.88 25.4,24.46 24.08,24.46 24.07,24.47 23.58,24.47 23.23,24.83 23.23,27.11 23.42,27.3
N11038315 on BOTTOM (solid shape): 4.93,37.7 4.93,35.89 4.52,34.92 4.29,35.86 4.04,34.95 3.71,35.84 3.71,35.83 3.71,37.69 3.72,37.7 4.29,37.7
N11038315 on TOP: 19.38,34.77 20.03,34.12 20.03,30.1 16.94,27.01 16.94,22.56 18.36,21.13 18.36,5.08 18.44,5 18.64,5 18.72,5.08 18.72,18.16 19.08,18.52 22.15,18.52 23.77,20.14 24.69,20.14 25.2,19.63 25.2,18.44 24.77,18.01 24.03,18.01 22.9,16.88 22.9,16.87 22.43,16.4 22.43,15.37 20.55,13.49 20.55,9.22 19.91,8.59 19.91,7.21 20.33,6.79 20.33,3.57 20.35,3.56 20.35,2.9 19.91,2.46 17.42,2.46 16.89,3 16.89,9.45 17.3,9.86 17.3,10.95 16.81,11.43 16.81,15.42 14.25,17.98 14.25,21.01 14.33,21.08 14.33,26.52 14.34,26.53 14.34,28.13 10.92,31.55 8.46,31.55 3.33,36.68 3.33,37.9 3.76,38.33 5.74,38.33 9.3,34.77
N11038315 on BOTTOM: 4.95,38.33 5.36,37.92 5.36,36.63 4.98,36.25 2.03,36.25 1.42,36.86 1.42,37.87 1.88,38.33
N11038315 on BOTTOM: 13.73,20.1 14.47,19.37 15.53,19.37 16.74,20.57 16.74,20.88 15.44,22.17 15.44,25.98 18.59,29.13 18.59,29.16 18.85,29.41 18.85,34.49 18.57,34.77 13.77,34.77 12.67,33.68 12.67,30.94 13.73,29.88
N11038315 on BOTTOM: 24.18,17.91 27.28,17.91 27.28,19.41 26.77,19.91 23.98,19.91 23.52,19.46 23.52,18.57
N11038315 on BOTTOM: 18.34,5.26 18.34,5.21 20.93,2.62 23.57,2.62 23.72,2.46 23.72,0.81 23.7,0.79 18.9,0.79 16.57,3.11 16.57,4.28 17.55,5.26
N11038315 on INNER1: 19.38,34.77 20.02,34.14 20.02,29.36 15.72,25.07 15.72,21.95 16.79,20.88 16.79,18.57 16.31,18.08 14.1,18.08 13.73,18.45 13.73,25.82 15.93,28.02 15.93,30.76 14.12,32.56 7.42,32.56 3.3,36.68 3.3,37.87 3.76,38.33 5.74,38.33 9.3,34.77
N11038315 on INNER2: 19.41,34.77 19.41,34.75 20.04,34.11 20.04,29.39 16.94,26.29 16.94,20.52 15.54,19.13 14.88,19.13 13.72,20.29 13.72,25.91 15.96,28.16 15.96,29.88 14.33,31.52 6.17,31.52 0.91,36.78 0.91,38.05 1.19,38.33 5.74,38.33 9.3,34.77
N11038383 on BOTTOM: 23.34,20.62 26.75,20.62 27.28,21.16 27.28,22.73 25.76,22.73 25.76,21.79 25.1,21.13 22.5,21.13 22.43,21.06 22.43,19.74 22.86,19.74 22.86,20.14
N11093530 on BOTTOM (solid shape): 53.7,17.68 49.66,17.68 49.66,21.89 53.7,21.89
N11093530 on BOTTOM (solid shape): 56.92,11.99 52.88,11.99 52.88,16.21 56.92,16.21
N11093530 on TOP: 57.81,20.75 57.94,20.62 57.94,12.32 57.4,11.79 55.12,11.79 54.38,12.52 54.38,20.17 54.97,20.75
N11093530 on BOTTOM: 54.38,21.54 55.07,20.85 57.89,20.85 58.14,20.6 58.14,11.96 57.68,11.51 53.34,11.51 52.78,12.06 52.78,17.32 52.48,17.63 49.68,17.63 49.5,17.81 49.5,22.23 49.1,22.63 49.1,27.89 49.17,27.97 53.92,27.97 53.98,27.91 53.98,27.1 54.38,26.7
N11093530 on BOTTOM: 43.76,6.73 43.76,5.16 43.97,4.95 44.6,4.95 44.68,5.03 44.68,6.71 44.65,6.73
N11093530 on INNER1: 58.12,12.06 57.84,11.79 52.45,11.79 51.64,12.6 51.64,16.26 51.82,16.43 51.82,17.42 51.65,17.59 48.76,17.59 48.49,17.86 48.49,22.45 50.57,24.54 53.44,24.54 53.86,24.12 53.86,21.93 55.27,20.52 57.91,20.52 58.12,20.32
N11118683 on BOTTOM: 16.18,11.63 17.73,11.63 18.77,10.59 18.77,8.84 18.72,8.79 18.52,8.79 18.52,10.46 18.19,10.79 17.25,10.79 16.94,10.49 16.94,10.13 16.74,9.93 16.41,9.93 16.18,10.16
N11134278 on BOTTOM: 47.27,21.49 47.27,22.23 47.65,22.61 48.18,22.61 48.54,22.25 48.54,21.49
N11134278 on BOTTOM: 50.77,17.04 51.54,17.04 51.77,16.81 51.77,15.82 50.5,15.82 50.5,16.76
N11138918 on BOTTOM: 46.2,9.37 46.2,7.75 46.38,7.57 46.86,7.57 46.91,7.62 46.91,9.35 46.79,9.47 46.3,9.47
N11256131 on BOTTOM: 17.75,19.74 17.75,21.44 16.36,22.83 16.36,25.98 19.58,29.21 19.58,29.97 20.35,29.97 20.5,29.82 20.5,28.91 16.94,25.35 16.94,23.34 17.64,22.64 17.65,22.64 17.77,22.53 18.52,22.53 18.52,21.51 18.24,21.51 18.14,21.41 18.14,19.74
N11515908 on BOTTOM: 20.62,26.8 20.62,28.04 21.08,28.5 21.08,29.97 22.28,31.17 23.7,31.17 23.72,31.14 23.72,29.74 23.67,29.69 22.58,29.69 21.89,29.01 21.89,26.8 21.87,26.77 20.65,26.77
N12555875 on BOTTOM: 41.53,13.44 42.72,13.44 43.23,12.93 44.45,12.93 44.45,12.09 44.4,12.04 42.6,12.04 42.39,12.24 41.53,12.24 41.45,12.32 41.45,13.36
N13144639 on TOP: 52.5,18.87 53.77,18.87 54.05,18.59 54.05,14.83 53.82,14.61 51.92,14.61 51.69,14.83 51.69,16.38 52.4,17.09 52.4,18.77
N13180601 on BOTTOM: 42.32,25.91 43.59,25.91 43.59,26.64 43.56,26.67 43.56,29.18 44.3,29.92 46.2,29.92 46.41,30.12 46.41,33.02 46.28,33.15 45.36,33.15 42.32,30.1
N13197624 on TOP: 48.72,33.93 49.96,33.93 50.16,33.73 50.16,31.72 50.01,31.57 48.18,31.57 47.85,31.9 47.85,33.07
N13197624 on BOTTOM: 49.76,33.76 48.16,33.76 48.16,33.73 47.88,33.45 47.88,31.9 47.93,31.85 49.53,31.85 50.22,32.54 50.22,33.3
N13230820 on TOP: 22.35,23.42 22.35,22.23 22.96,21.62 24.71,21.62 25.27,22.17 25.27,23.06 24.71,23.62 22.56,23.62
N13230820 on BOTTOM: 27.66,24.46 27.66,23.19 27.64,23.16 25.55,23.16 25.02,22.63 25.02,22.35 24.56,21.89 23.55,21.89 23.04,22.4 23.04,23.77 23.72,24.46
N13361044 on BOTTOM: 26.26,24.99 26.26,27.36 25.83,27.79 24.77,27.79 24.77,30.51 25.43,31.17 27.18,31.17 27.69,30.66 27.69,24.97 26.29,24.97
N13361044 on BOTTOM: 20.42,7.8 20.42,5.97 20.55,5.84 20.98,5.84 21.01,5.87 21.01,7.87 20.9,7.98 20.6,7.98
N13388475 on BOTTOM (solid shape): 4.27,33.48 4.52,34.39 4.85,33.5 4.85,33.51 4.85,31.65 4.84,31.64 4.27,31.64 3.63,31.65 3.63,33.45 4.04,34.42
N13388475 on TOP: 11.43,21.79 11.43,24.16 11.09,24.5 7.28,24.5 6.3,23.52 6.3,22.66 4.8,21.16 4.78,21.16 2.59,18.97 2.59,17.09 2.36,16.87 0.58,16.87 0.23,17.22 0.23,33.48 0.43,33.68 3.53,33.68 6.02,31.19 6.81,31.19 7.9,30.1 7.9,28.09 9.21,26.78 12.69,26.78 13.26,26.21 13.26,22.12 12.83,21.69 12.83,17.11 11.95,16.23 11.95,13.02 11.91,12.98 9.04,12.98 8.79,13.23 8.79,19.15
N13388475 on BOTTOM: 3.73,16.84 0.58,16.84 0.23,17.2 0.23,29.01 0.24,29.02 0.24,32.7 0.43,32.89 6.43,32.89 6.43,21.54 7.11,20.85 7.11,12.57 6.86,12.32 4.27,12.32 4.14,12.45 4.14,14.12 4.11,14.15 4.11,16.46
N13388475 on INNER1: 6.45,17.55 5.74,16.84 0.61,16.84 0.25,17.2 0.25,30.86 0.71,31.32 6.25,31.32 6.45,31.11
N13388475 on INNER2: 2.39,16.84 2.37,16.85 0.6,16.85 0.23,17.22 0.23,29.01 1.12,29.9 6.25,29.9 6.58,29.57 6.58,17.02 6.4,16.84
N13388575 on TOP: 13.64,0.84 13.64,2.67 11.38,4.93 4.22,4.93 4.22,10.01 4.25,10.05 4.24,10.06 4.24,11.07 4.62,11.46 12.52,11.46 13,11.94 13,14.91 13.49,15.39 14.63,15.39 15.14,14.88 15.14,8.26 15.6,7.8 15.6,5.49 15.27,5.16 15.27,3.73 15.6,3.4 15.6,0.66 15.19,0.25 14.22,0.25
N13388575 on BOTTOM: 13,14.73 13,6.4 13.55,5.85 13.54,5.84 13.54,1.12 14.15,0.51 15.01,0.51 15.52,1.02 15.52,7.85 15.06,8.31 15.06,14.73 14.5,15.29 13.56,15.29
N13388575 on INNER1: 13.56,0.99 13.56,3 11.79,4.78 4.39,4.78 4.14,5.03 4.14,14.99 4.78,15.62 14.61,15.62 15.11,15.11 15.11,8.36 15.65,7.82 15.65,1.02 15.01,0.38 14.17,0.38
N13388575 on INNER2: 12.83,14.86 12.83,4.85 13.46,4.22 13.46,0.91 14.07,0.3 14.99,0.3 15.54,0.86 15.54,7.87 14.96,8.46 14.96,14.91 14.48,15.39 13.36,15.39
N13388715 on BOTTOM (solid shape): 10.39,33.22 10.64,34.14 10.97,33.25 10.98,33.26 10.98,31.4 10.96,31.38 10.39,31.38 9.75,31.39 9.75,33.2 10.16,34.16
N13388715 on TOP: 8.59,23.27 9.65,23.27 10.11,22.81 10.11,22.02 7.26,19.18 7.26,17.73 7.29,17.7 7.29,13.03 7.21,12.95 4.22,12.95 4.17,13 4.17,18.85
N13388715 on BOTTOM: 8.81,21.06 7.77,22.1 7.77,32.79 7.95,32.97 11.4,32.97 11.4,30.24 12.74,28.91 12.74,27.75 12.73,27.74 12.73,20.29 11.76,19.33 11.81,19.28 11.81,12.42 11.73,12.34 8.99,12.34 8.81,12.52
N13388715 on INNER1: 12.6,26.24 13.79,27.43 13.79,30.43 13.28,30.94 8.41,30.94 7.77,30.3 7.77,16.89 7.82,16.84 12.4,16.84 12.6,17.04
N13388715 on INNER2: 12.6,26.26 13.79,27.46 13.79,29.26 13.18,29.87 12.12,29.87 12.1,29.86 8.78,29.86 8.74,29.82 8.23,29.82 7.92,29.51 7.92,17.12 8.15,16.89 12.24,16.89 12.6,17.25
N13388781 on TOP: 2.79,15.27 2.51,15.54 0.86,15.54 0.2,14.88 0.2,1.47 0.41,1.27 2.87,1.27 3.16,1.56 3.16,3.7 2.79,4.06
N13388781 on BOTTOM: 11.56,4.8 11.81,5.05 11.81,10.52 11.61,10.72 3.33,10.72 2.79,11.25 2.79,15.21 2.46,15.54 0.89,15.54 0.23,14.88 0.23,0.58 0.58,0.23 2.72,0.23 3.17,0.69 3.17,3.3 3.19,3.31 3.19,3.82 4.17,4.8
N13388781 on INNER1: 2.54,15.54 0.89,15.54 0.2,14.86 0.2,1.5 0.43,1.27 3.78,1.27 4.32,1.8 4.32,2.54 2.84,4.01 2.84,15.24
N13388781 on INNER2: 11.35,15.57 11.58,15.34 11.58,5.59 10.57,4.57 7.19,4.57 5.08,2.46 5.08,0.28 5.03,0.23 0.56,0.23 0.2,0.58 0.2,14.88 0.89,15.57
N13388817 on TOP: 10.29,1.7 10.29,0.56 9.86,0.13 6.83,0.13 6.4,0.56 6.4,1.57 7.11,2.29 9.7,2.29
N13388817 on BOTTOM: 10.29,1.7 10.29,0.56 9.86,0.13 6.83,0.13 6.4,0.56 6.4,1.57 7.04,2.21 9.78,2.21
N13388817 on INNER1: 10.24,1.68 10.24,0.53 9.8,0.1 6.78,0.1 6.35,0.53 6.35,1.55 7.06,2.26 9.65,2.26
N13388817 on INNER2: 10.29,1.73 10.29,0.58 9.86,0.15 6.83,0.15 6.4,0.58 6.4,1.6 7.11,2.31 9.7,2.31
N13395881 on BOTTOM: 45.06,12.95 45.06,11.73 44.78,11.46 43.79,11.46 43.76,11.43 43.76,10.64 44.78,10.64 45.9,11.76 45.9,12.9 45.85,12.95
N13395881 on BOTTOM: 42.29,24.21 42.29,22.28 42.57,22 43,22 43.18,22.17 43.18,22.78 43.59,23.19 43.59,24.1 43.46,24.23 42.32,24.23
N13397632 on BOTTOM: 42.01,11.48 42.01,8.92 42.09,8.84 42.75,8.84 42.88,8.97 42.88,11.4 42.77,11.51 42.04,11.51

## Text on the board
Ref Des/Silkscreen Bottom: SN
Ref Des/Silkscreen Top: 2303 | REV B | DER-979
User.5: 11.  TRACE SPACE +/- 0.003" | 13. 4 LAYERS BOARD TOP,INNER1,INNER2,BOT.
User.8: FIGURE | FINISHED_SIZE | 12.0 | 18.0 | 20.0 | 30.0 | 40.0 | 50.0 | 81.0 | DRILL CHART: TOP to BOTTOM | ALL UNITS ARE IN MILS | TOLERANCE_DRILL | +0.0/-0.0 | +3.0/-3.0 | PLATED | QTY | 10 | 230 | 1 | 18 | 4 | 2
